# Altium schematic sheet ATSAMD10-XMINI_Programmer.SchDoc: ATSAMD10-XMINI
size A3; Organization: ATMEL Norway; Address1: Vestre Rosten 79; Address2: N-7075 TILLER; Address3: NORWAY; DocumentNumber: A09-2378; Revision: 2; SheetNumber: 3; SheetTotal: 3; PageSetup: Record=PageOptions¦CenterHorizontal=True¦CenterVertical=True¦PrintScale=1.01¦XCorrection=1.00¦YCorrection=1.00¦PrintKind=1¦BorderSize=5000000¦LeftOffset=0¦BottomOffset=0¦Orientation=2¦PaperLength=1000¦PaperWidth=1000¦Scale=100¦PaperSource=7¦PrintQuality=-4¦MediaType=1¦DitherType=10¦PaperKind=A3 (297 x 420 mm)¦PrintScaleMode=1
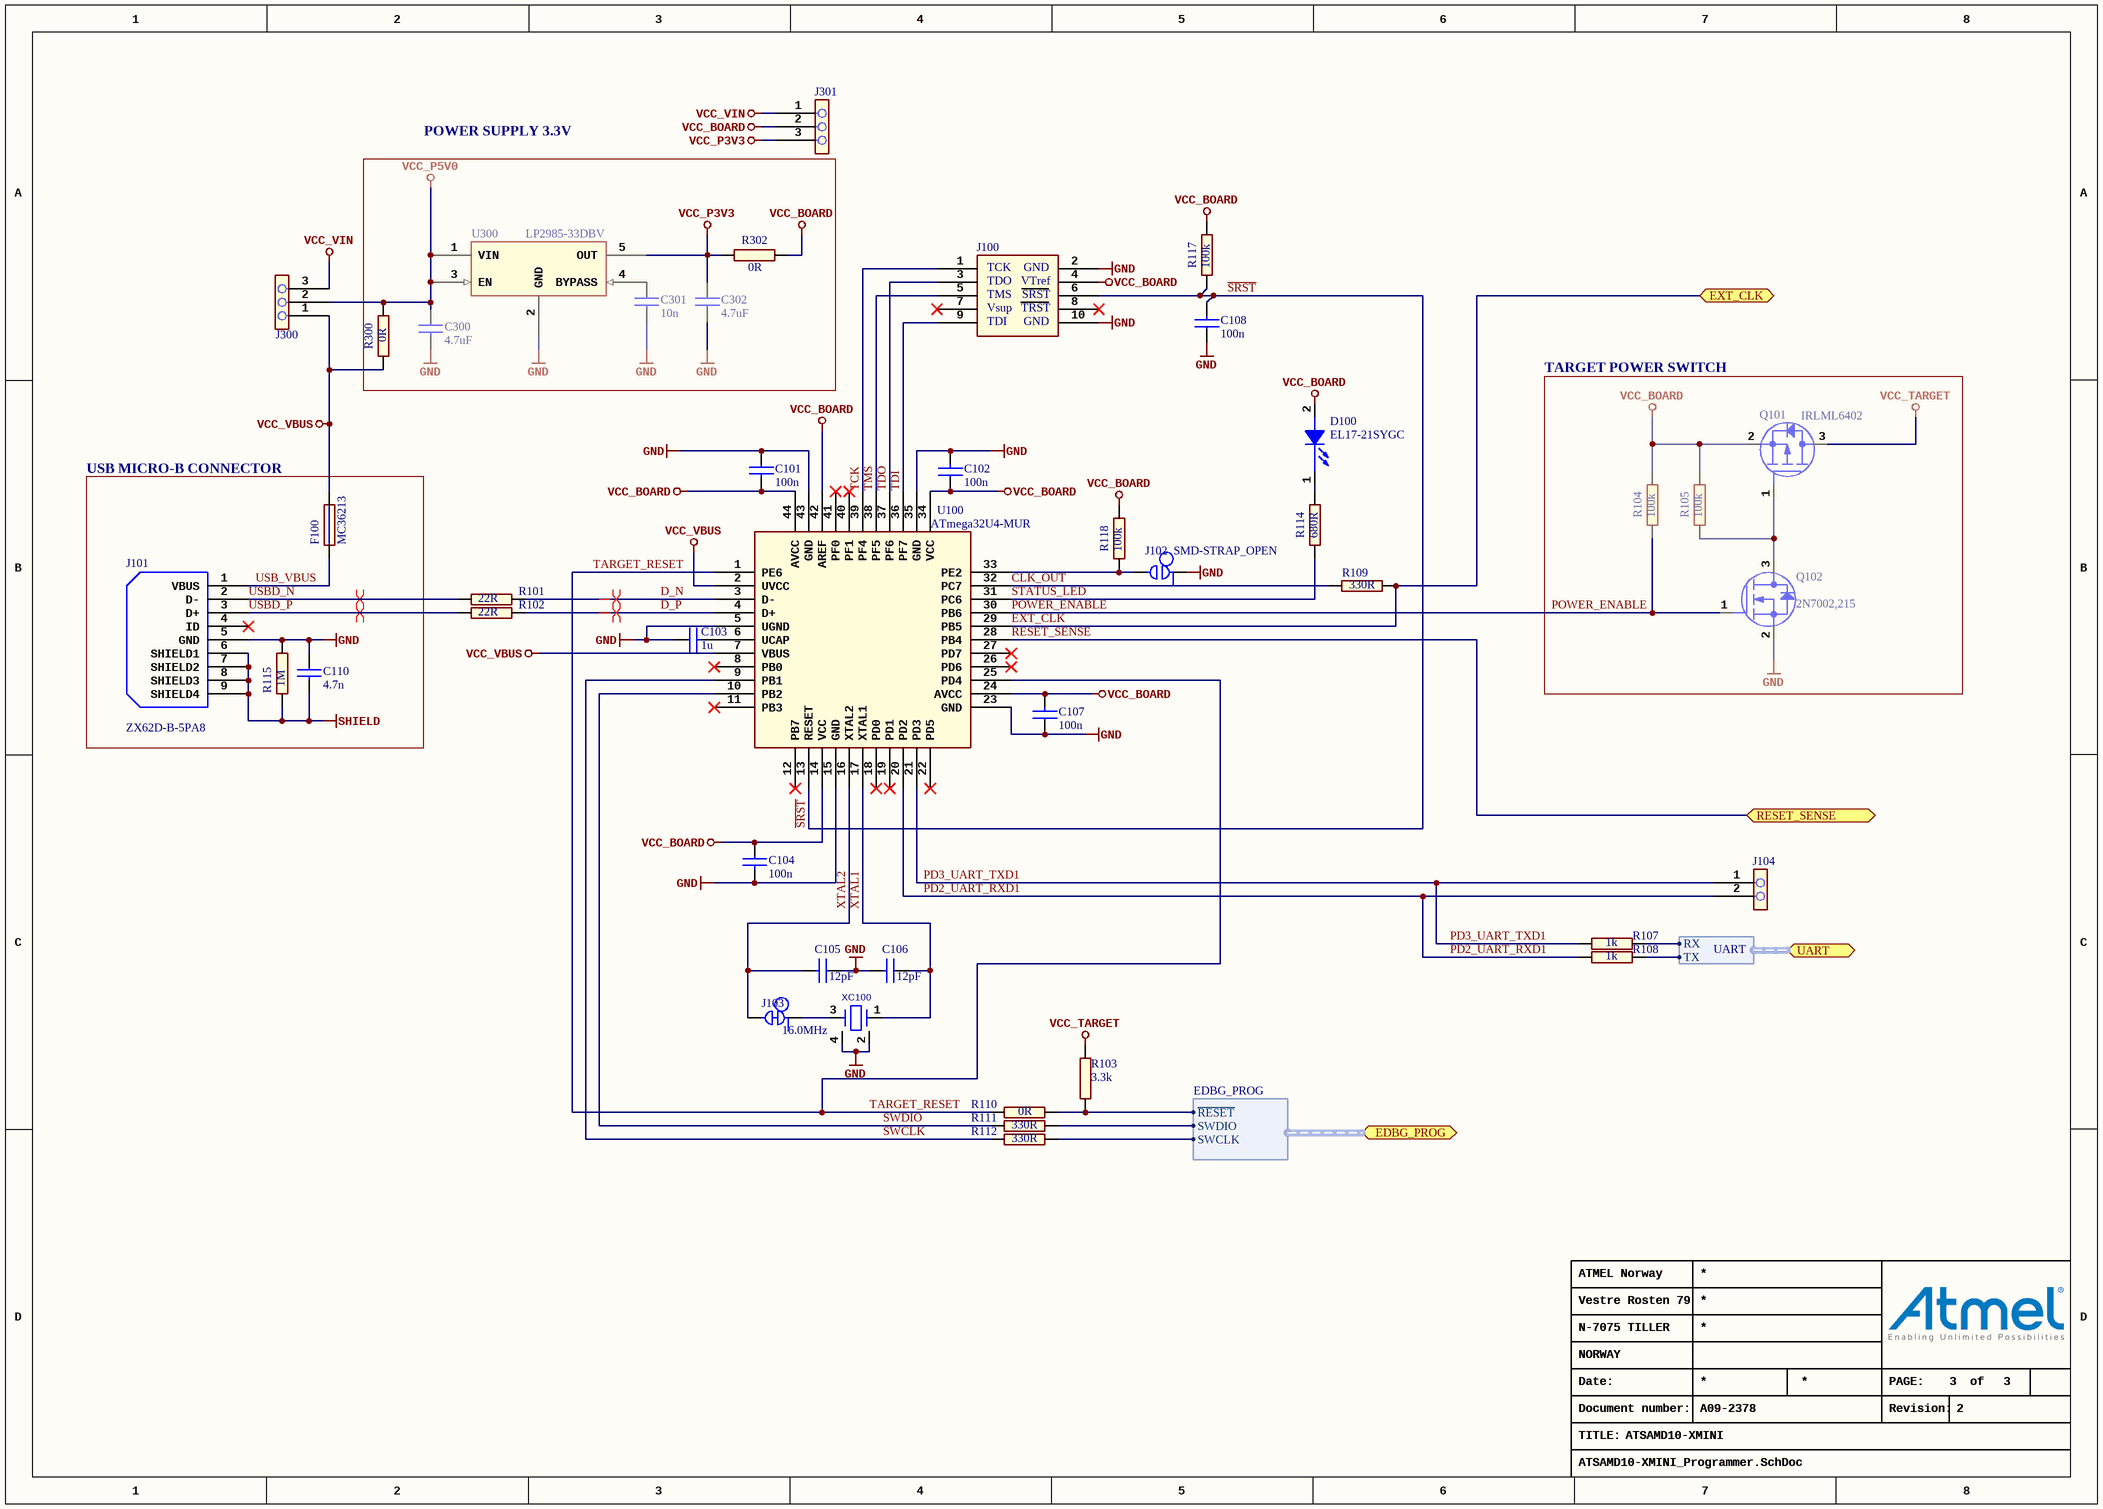
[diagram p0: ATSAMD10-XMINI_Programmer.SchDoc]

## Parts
C101  value 100n  [AP1-00001]
C102  value 100n  [AP1-00001]
C103  value 1u  [AP1-00001]
C104  value 100n  [AP1-00001]
C105  value 12pF  [AP1-00038]
C106  value 12pF  [AP1-00038]
C107  value 100n  [AP1-00001]
C108  value 100n  [AP1-00001]
C110  value 4.7n  [AP1-00001]
C300  value 4.7uF  [AP1-00002]  (hidden comment: Farnell no.: 1833806)
C301  value 10n  [AP1-00001]
C302  value 4.7uF  [AP1-00002]  (hidden comment: Farnell no.: 1833806)
D100  value EL17-21SYGC  [AP4-00013]
F100  value MC36213  [AP2-00002]  (hidden comment: Farnell no: 1861197)
J100  (no value)  [AP8-00257]
J101  value ZX62D-B-5PA8  [AP8-00851]  (hidden comment: 2,000 pieces per reel)
J102  value SMD-STRAP_OPEN  [AP9-00034]  (net tie, no BOM)
J103  (no value)  [AP9-00044]  (net tie, no BOM)
J104  (no value)  [AP8-00733]
J300  (no value)  [AP8-00745]
J301  (no value)  [AP8-00745]
Q101  value IRLML6402  [AP5-00002]
Q102  value 2N7002,215  [AP5-00002]
R101  value 22R  [AP2-00000]
R102  value 22R  [AP2-00000]
R103  value 3.3k  [AP2-00000]
R104  value 100k  [AP2-00000]
R105  value 100k  [AP2-00000]
R107  value 1k  [AP2-00000]
R108  value 1k  [AP2-00000]
R109  value 330R  [AP2-00000]
R110  value 0R  [AP2-00000]
R111  value 330R  [AP2-00000]
R112  value 330R  [AP2-00000]
R114  value 680R  [AP2-00000]
R115  value 1M  [AP2-00000]
R117  value 100k  [AP2-00000]
R118  value 100k  [AP2-00000]
R300  value 0R  [AP2-00000]
R302  value 0R  [AP2-00000]
U100  value ATmega32U4-MUR  [AP6-00375]
U300  value LP2985-33DBV  [AP6-00087]
XC100  value 16.0MHz  [AP7-00061]

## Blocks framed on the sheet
POWER SUPPLY 3.3V: C300-C302 R300 R302 U300
TARGET POWER SWITCH: Q101 Q102 R104 R105
USB MICRO-B CONNECTOR: C110 F100 J101 R115

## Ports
EDBG_PROG (harness EDBG_PROG), EXT_CLK (bidir), RESET_SENSE, UART (harness UART)

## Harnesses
UART: RX, TX
EDBG_PROG: ~{RESET}, SWDIO, SWCLK

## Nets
GND: C101.1 C102.2 C103.1 C104.2 C105.1 C106.2 C107.1 C108.1 C110.1 C300.2 C301.2 C302.2 J100.2 J100.10 J101.5(GND) J102.1 Q102.2(S) R115.2 U100.5(UGND) U100.15(GND) U100.23(GND) U100.35(GND) U100.43(GND) U100.45(GND) U300.2(GND) XC100.2(GND) XC100.4(GND)
SHIELD: C110.2 J101.6(SHIELD1) J101.7(SHIELD2) J101.8(SHIELD3) J101.9(SHIELD4) R115.1
VCC_BOARD: C101.2 C102.1 C104.1 C107.2 D100.2(ANODE) J100.4 J301.2 Q101.2(S) R104.2 R105.2 R117.2 R118.2 R302.2 U100.14(VCC) U100.24(AVCC) U100.34(VCC) U100.42(AREF) U100.44(AVCC)
VCC_P3V3: C302.1 J301.3 R302.1 U300.5(OUT)
VCC_P5V0: C300.1 J300.2 R300.2 U300.1(VIN) U300.3(EN)
VCC_TARGET: Q101.3(D) R103.2
VCC_VBUS: F100.2 J300.1 R300.1 U100.2(UVCC) U100.7(VBUS)
VCC_VIN: J300.3 J301.1
CLK_OUT: R109.2 U100.32(PC7)
D_N: R101.2 U100.3(D-)
D_P: R102.2 U100.4(D+)
EXT_CLK: R109.1 U100.29(PB5) ; port EXT_CLK
PD2_UART_RXD1: J104.2 R108.1 U100.20(PD2)
PD3_UART_TXD1: J104.1 R107.1 U100.21(PD3)
POWER_ENABLE: Q102.1(G) R104.1 U100.30(PB6)
RESET_SENSE: U100.28(PB4) ; port RESET_SENSE
~{SRST}: C108.2 J100.6 R117.1 U100.13(RESET)
STATUS_LED: R114.2 U100.31(PC6)
SWCLK: R112.1 U100.9(PB1)
SWDIO: R111.1 U100.10(PB2)
TARGET_RESET: R110.1 U100.1(PE6) U100.25(PD4)
TCK: J100.1 U100.39(PF4)
TDI: J100.9 U100.36(PF7)
TDO: J100.3 U100.37(PF6)
TMS: J100.5 U100.38(PF5)
USB_VBUS: F100.1 J101.1(VBUS)
USBD_N: J101.2(D-) R101.1
USBD_P: J101.3(D+) R102.1
XTAL1: C106.1 U100.17(XTAL1) XC100.1(IN)
XTAL2: C105.2 J103.2 U100.16(XTAL2)
NetC103_2: C103.2 U100.6(UCAP)
NetC301_1: C301.1 U300.4(BYPASS)
NetD100_1: D100.1(CATHODE) R114.1
NetJ102_2: J102.2 R118.1 U100.33(PE2)
NetJ103_1: J103.1 XC100.3(OUT)
NetQ101_1: Q101.1(G) Q102.3(D) R105.1
NetR103_1: R103.1 R110.2 ; port EDBG_PROG.~{RESET}
NetR107_2: R107.2 ; port UART.RX
NetR108_2: R108.2 ; port UART.TX
NetR111_2: R111.2 ; port EDBG_PROG.SWDIO
NetR112_2: R112.2 ; port EDBG_PROG.SWCLK

Not connected (* = marked no-connect by the designer): J100 7* 8*; J101 4(ID)*; U100 8(PB0)* 11(PB3)* 12(PB7)* 18(PD0)* 19(PD1)* 22(PD5)* 26(PD6)* 27(PD7)* 40(PF1)* 41(PF0)*

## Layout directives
differential pair: D_N, D_P, USBD_N, USBD_P

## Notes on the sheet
- Date:
- PAGE:
- of
- TITLE:
- Document number:
- Revision:

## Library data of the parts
C101 C102 C104 C107 C108 = A01-0246: Ceramic capacitor, SMD 0402, X7R, 16V, +/-10%; PartGroup: Capacitors,Ceramic,SMD 0402; Manufacturer: Kemet; MPN: C0402C104K4RACTU; TemperatureRange: -55 - +125 deg C
C103 = A01-0286: Ceramic capacitor, SMD 0402, X5R, 6.3V, +/-10% (de26942); PartGroup: Capacitors,Ceramic,SMD 0402; Manufacturer: Kemet; MPN: C0402C105K9PAC; TemperatureRange: -55 to 85 deg C
C105 C106 = A01-0355: Ceramic capacitor, SMD 0402, NP0, 50V, +/-5% (de19819); PartGroup: Capacitors,Ceramic,SMD 0402; Manufacturer: Kyocera-elco; MPN: CM05CG120J50AH; Tolerance: 5%; TemperatureRange: -55 - +125 deg C
C110 = A01-0046: Ceramic capacitor, SMD 0402, X7R, 25V, +/-10% (de35287); PartGroup: Capacitors,Ceramic,SMD 0402; Manufacturer: PHYCOMP; MPN: 2238 587 15632; TemperatureRange: -55 - +125 deg C
C300 C302 = A01-0502: Ceramic capacitor, SMD 0603, X5R, 10V, ±10 %; PartGroup: Capacitors,Ceramic,SMD 0603; Manufacturer: AVX; MPN: 0603ZD475KAT2A; Tolerance: Â±10%; TemperatureRange: Ã‚â€“55 to +85 deg C
C301 = A01-0050: Ceramic capacitor, SMD 0402, X7R, 25V, +/-10%; PartGroup: Capacitors,Ceramic,SMD 0402; Manufacturer: YAGEO CORP; MPN: CC0402KRX7R8BB103; TemperatureRange: -55 - +125 deg C
D100 = A10-0018: LED, Green, Wave length=575nm, SMD 0805, ±70°; PartGroup: Opto,LEDs,SMD; Manufacturer: Everlight; TemperatureRange: -40 - +85 deg C
F100 = A02-0622: Resetable PTC fuse, Ih = 0.5A, It = 1.0A, 0805 package; PartGroup: Resistors,Resettable fuses,SMD; Manufacturer: Multicomp; TemperatureRange: -40°C to + 85°C
J100 = A08-0385: 2x5 pin header, 1.27mm pitch, THM; PartGroup: Mechanical devices,Connectors,Pin headers; Manufacturer: Garry; MPN: 176-2-010-0-T-XS0-0730; Value: PIN HEADER 2x5
J101 = A08-2092: Micro USB B Connector, Standard SMT + DIP; PartGroup: Mechanical devices,Connectors,USB; Manufacturer: HIROSE; MPN: ZX62D-B-5PA8(30)
J102 = A09-0483: Default open SMD strap; PartGroup: Mechanical devices,PCB implemented components
J103 = A09-0783: Default closed SMD strap, 0603 size; PartGroup: Mechanical devices,PCB implemented components; Value: SMD-STRAP_0603_CLOSED
J104 = A08-1754: 1x2 pin header, 2.54mm pitch, Pin-in-Paste THM; PartGroup: Mechanical devices,Connectors,Pin headers; Manufacturer: SAMTEC; Value: HMTSW-102-23-F-S-237; TemperatureRange: - 55 deg C to + 125 deg C
J300 J301 = A08-1799: 1x3 pin header, 2.54mm pitch, Pin-in-Paste THM, 1mm hole; PartGroup: Mechanical devices,Connectors,Pin headers; Manufacturer: SAMTEC; Value: HMTSW-103-23-F-S-237
Q101 = A05-0087: P-ch. MOSFET. -30V, -3.7A continuous,RDS(ON)=0.05Ohm@VGS=-4,5V, RDS(ON)=0.08Ohm@VGS=-2.5V; PartGroup: Transistors,Power FET,SMD; Manufacturer: International Rectifier; MPN: IRLML6402PBF; TemperatureRange: -55 - +150 deg C
Q102 = A05-0085: N-Channel MOSFET. 60V, 0.300A continuous, 1.2A Peak. RDS(ON) = 3.8Ohm@VGS=4.5V, VGS(th)<2.5V; PartGroup: Transistors,Small signal FET,SMD; Manufacturer: NXP; TemperatureRange: -65 to 150 deg C
R101 R102 = A02-0172: Thick film resistor, SMD 0402, 1/16W, 1% (de23607); PartGroup: Resistors,SMD,0402 1%; Manufacturer: Samsung; MPN: RC100SF22R0CS; TemperatureRange: -55 - +125 deg C
R103 = A02-0224: Thick film resistor, SMD 0402, 1/16W, 1%; PartGroup: Resistors,SMD,0402 1%; Manufacturer: ASJ; MPN: CR10-3301-FK; TemperatureRange: -55 - +125 deg C
R104 R105 R117 R118 = A02-0260: Thick film resistor, SMD 0402, 1/16W, 1%; PartGroup: Resistors,SMD,0402 1%; Manufacturer: ASJ; MPN: CR10-1003-FK; TemperatureRange: -55ï¿½ to +125ï¿½C
R107 R108 = A02-0212: Thick film resistor, SMD 0402, 1/16W, 1%; PartGroup: Resistors,SMD,0402 1%; Manufacturer: ASJ; MPN: CR10-1001-FK; TemperatureRange: -55 - +125 deg C
R109 R111 R112 = A02-0200: Thick film resistor, SMD 0402, 1/16W, 1%; PartGroup: Resistors,SMD,0402 1%; Manufacturer: ASJ; MPN: CR10-3300-FK; TemperatureRange: -55 - +125 deg C
R110 R300 R302 = A02-0163: RES 0.0 OHM 1/16W 0402 SMD; PartGroup: Resistors,SMD,0402 1%; Manufacturer: (n/a); MPN: RMCF0402ZT0R00; Tolerance: 1 %; TemperatureRange: -55 - +125 deg C
R114 = A02-0208: Thick film resistor, SMD 0402, 1/16W, 1%; PartGroup: Resistors,SMD,0402 1%; Manufacturer: ASJ; MPN: CR10-6800-FK; TemperatureRange: -55 - +125 deg C
R115 = A02-0284: Thick film resistor, SMD 0402, 1/16W, 1%; PartGroup: Resistors,SMD,0402 1%; Manufacturer: ASJ; MPN: CR10-1004-FK; TemperatureRange: -55 - +125 deg C
U100 = A06-0305: ATmega32U4 QFN package; PartGroup: Integrated Circuits,MCU, MPU, DSP,AVR MCU; Manufacturer: ATMEL
U300 = A06-1099: LDO 3.3V 150mA SOT23-5 1.5% (cer. cap); PartGroup: Integrated Circuits,Regulators,Linear; Manufacturer: Texas Instruments; TemperatureRange: -40 - +125 deg. C
XC100 = A07-0078: 16MHz uXtal, 3.2 x 2.5 mm SMD, CL=9pF, 15PPM, ESR=80ohm(Max.; PartGroup: Frequency devices,Crystals,SMD; Manufacturer: Epson Toyocom; MPN: TSX-3225 16.0000MF09Z-AC3; TemperatureRange: -40Â°C to +85Â°C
